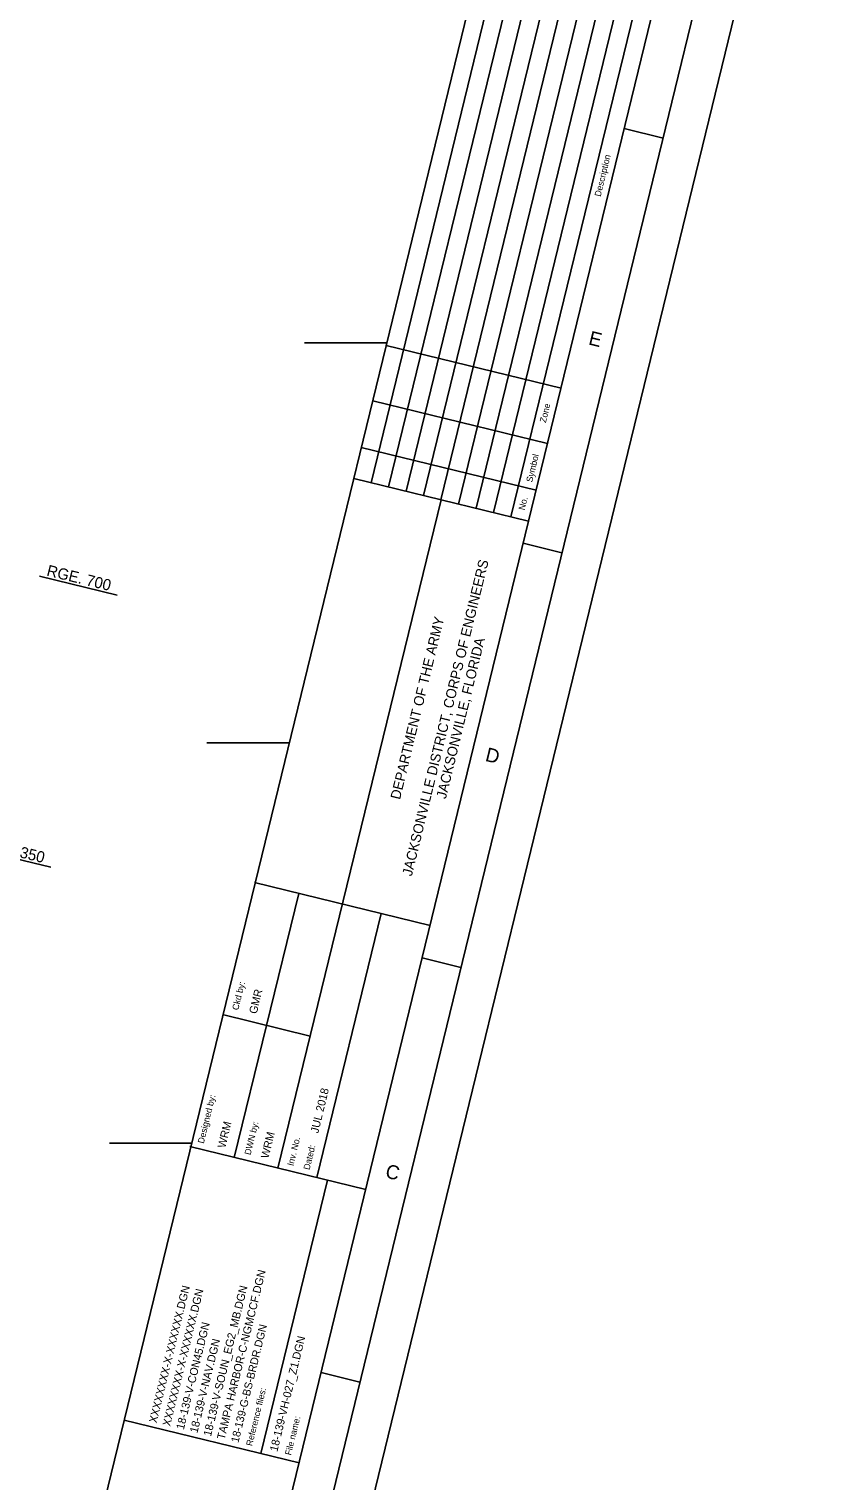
# Model space of a CAD drawing. Extents: x 409260 to 414340, y 1188556 to 1192902.
# Drawn here: x 413349 to 414340, y 1189578 to 1191392 of the extents above; entities that cross this region are included whole.
import ezdxf

# ---------------------------------------------------------------- set-up
doc = ezdxf.new("R2010")
doc.units = 0
for name, color, linetype in [('G-ANNO-NPLT', 7, 'Continuous'), ('G-ANNO-TEXT-DRWG', 7, 'Continuous'), ('G-ANNO-TEXT-PROJ', 7, 'Continuous'), ('G-ANNO-TEXT-TTLB', 7, 'Continuous'), ('G-ANNO-TTLB', 7, 'Continuous'), ('V-ALGN-TEXT', 7, 'Continuous'), ('V-TOPO-COOR-STAT', 7, 'Continuous')]:
    doc.layers.add(name, color=color, linetype=linetype)

msp = doc.modelspace()

# ---------------------------------------------------------------- linework, layer by layer
at = {"layer": 'G-ANNO-NPLT'}
msp.add_lwpolyline([(410065.6, 1192901.9), (414340.3, 1191859.4), (413534.7, 1188556.2), (409260, 1189598.7)], close=True, dxfattribs=at)
at = {"layer": 'G-ANNO-TTLB'}
for p, q in [((414000.8, 1191839.2), (413242.6, 1188730.4)), ((413975, 1191639.3), (413776.5, 1190825.2)), ((413996.9, 1191634), (413798.4, 1190819.9)), ((414018.8, 1191628.6), (413820.2, 1190814.6)), ((414040.6, 1191623.3), (413842.1, 1190809.3)), ((414062.5, 1191618), (413863.9, 1190803.9)), ((414084.3, 1191612.6), (413885.8, 1190798.6)), ((414106.2, 1191607.3), (413907.7, 1190793.3)), ((414128.1, 1191602), (413929.5, 1190787.9)), ((414149.9, 1191596.7), (413951.4, 1190782.6)), ((414141.6, 1191255.8), (414093, 1191267.6)), ((413795.4, 1190996.7), (414014, 1190943.4)), ((413778.5, 1190927.5), (413997.1, 1190874.2)), ((413764.3, 1190869.2), (413982.9, 1190815.9)), ((413754.8, 1190830.5), (413973.4, 1190777.2)), ((413659.8, 1189968.9), (413864.1, 1190803.9)), ((413864.1, 1190803.9), (413855.7, 1190769.5)), ((414015.2, 1190737.7), (413966.7, 1190749.5)), ((413630.9, 1190325.6), (413850.3, 1190272.1)), ((413605.5, 1189982.2), (413686.2, 1190312.1)), ((413789.1, 1190287), (413708.6, 1189957)), ((413888.9, 1190219.5), (413840.3, 1190231.4)), ((413590.6, 1190160.6), (413700.2, 1190133.9)), ((413550, 1189995.7), (413769.8, 1189942.1)), ((413721.9, 1189953.8), (413638.6, 1189612.4)), ((413762.5, 1189701.4), (413714, 1189713.3)), ((413467.9, 1189654.1), (413686.5, 1189600.7))]:
    msp.add_line(p, q, dxfattribs=at)
for points in [[(409320.4, 1189635.4), (413498, 1188616.6), (414279.8, 1191822.7), (410102.3, 1192841.4)], [(414219.4, 1191785.9), (410211.9, 1192763.3), (409453.7, 1189654.4), (413461.3, 1188677.1)]]:
    msp.add_lwpolyline(points, close=True, dxfattribs=at)
at = {"layer": 'V-ALGN-TEXT'}
for p, q in [((413361.8, 1190708.4), (413459, 1190684.8)), ((413278.9, 1190368.4), (413376.1, 1190344.7))]:
    msp.add_line(p, q, dxfattribs=at)
at = {"layer": 'V-TOPO-COOR-STAT'}
for p, q in [((413693.2, 1191000), (413796.1, 1191000)), ((413571.3, 1190500), (413674.2, 1190500)), ((413449.3, 1190000), (413552.3, 1190000))]:
    msp.add_line(p, q, dxfattribs=at)

# ---------------------------------------------------------------- texts
at = {"layer": 'G-ANNO-TEXT-DRWG'}
for s, p in [('GMR', (413633.4, 1190160.8)), ('WRM', (413594.1, 1189993.3)), ('WRM', (413648.2, 1189980.3)), ('TAMPA HARBOR-C-NGMCCF.DGN', (413593.3, 1189629)), ('XXXXXXXX-X-XXXXXX.DGN', (413508.3, 1189649.7)), ('XXXXXXXX-X-XXXXXX.DGN', (413525.3, 1189645.6)), ('18-139-V-SOUN_EG2_MB.DGN', (413576.3, 1189633.1)), ('18-139-V-CON45.DGN', (413542.3, 1189641.4)), ('18-139-V-NAV.DGN', (413559.3, 1189637.3)), ('18-139-VH-027_Z1.DGN', (413659.3, 1189614))]:
    msp.add_text(s, height=10, rotation=76.2946, dxfattribs=at).set_placement(p)
at = {"layer": 'G-ANNO-TEXT-PROJ'}
for s, height, p in [('JUL 2018', 10, (413710.3, 1190011.8)), ('18-139-G-BS-BRDR.DGN', 9.8, (413610.6, 1189625.2))]:
    msp.add_text(s, height=height, rotation=76.2946, dxfattribs=at).set_placement(p)
at = {"layer": 'G-ANNO-TEXT-TTLB'}
for s, height, p in [('Description', 8, (414063.5, 1191182.1)), ('Zone', 8, (413995, 1190899.6)), ('Symbol', 8, (413978, 1190825.2)), ('No.', 8, (413968.5, 1190790.3)), ('JACKSONVILLE DISTRICT, CORPS OF ENGINEERS', 12.5, (413827.4, 1190333)), ('DEPARTMENT OF THE ARMY', 12.5, (413812.6, 1190428.6)), ('JACKSONVILLE, FLORIDA', 12.5, (413870, 1190429.5)), ('Ckd by:', 8, (413610.4, 1190165.6)), ('Designed by:', 8, (413567.3, 1189999)), ('DWN by:', 8, (413625.8, 1189984.7)), ('Inv. No.', 8, (413679.3, 1189971)), ('Dated:', 8, (413699.5, 1189966.1)), ('Reference files:', 8, (413627.8, 1189621.1)), ('File name:', 8, (413676.4, 1189609.5))]:
    msp.add_text(s, height=height, rotation=76.2946, dxfattribs=at).set_placement(p)
at = {"layer": 'G-ANNO-TTLB'}
for s, p in [('E', (414047.4, 1190998.1)), ('D', (413918.3, 1190477.8)), ('C', (413793.3, 1189957.3))]:
    msp.add_text(s, height=17.5, rotation=346.2946, dxfattribs=at).set_placement(p)
at = {"layer": 'V-ALGN-TEXT'}
for s, p in [('RGE. 700', (413370, 1190709.3)), ('RGE. 350', (413287.1, 1190369.3))]:
    msp.add_text(s, height=13.92, rotation=346.2946, dxfattribs=at).set_placement(p)

doc.saveas('drawing.dxf')
